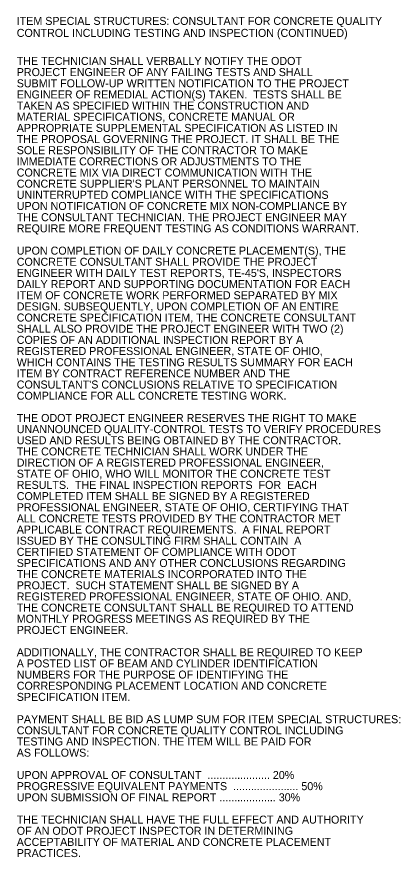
# Model space of a CAD drawing. Extents: x 0 to 55.2, y -1 to 22.
# Drawn here: x 48.5 to 55.22, y -0.99 to 13.7 of the extents above; entities that cross this region are included whole.
import ezdxf

# ---------------------------------------------------------------- set-up
doc = ezdxf.new("R2010")
doc.units = 0
doc.layers.add('SH_Text', color=7, linetype='Continuous')

msp = doc.modelspace()

# ---------------------------------------------------------------- texts
at = {"layer": 'SH_Text'}
for s, p in [('ITEM SPECIAL STRUCTURES: CONSULTANT FOR CONCRETE QUALITY', (48.503, 13.56)), ('CONTROL INCLUDING TESTING AND INSPECTION (CONTINUED)', (48.503, 13.35)), ('THE TECHNICIAN SHALL VERBALLY NOTIFY THE ODOT', (48.503, 12.86)), ('PROJECT ENGINEER OF ANY FAILING TESTS AND SHALL', (48.503, 12.665)), ('SUBMIT FOLLOW-UP WRITTEN NOTIFICATION TO THE PROJECT', (48.503, 12.469)), ('ENGINEER OF REMEDIAL ACTION(S) TAKEN.  TESTS SHALL BE', (48.503, 12.274)), ('TAKEN AS SPECIFIED WITHIN THE CONSTRUCTION AND', (48.503, 12.079)), ('MATERIAL SPECIFICATIONS, CONCRETE MANUAL OR', (48.503, 11.884)), ('APPROPRIATE SUPPLEMENTAL SPECIFICATION AS LISTED IN', (48.503, 11.689)), ('THE PROPOSAL GOVERNING THE PROJECT. IT SHALL BE THE', (48.503, 11.494)), ('SOLE RESPONSIBILITY OF THE CONTRACTOR TO MAKE', (48.503, 11.299)), ('IMMEDIATE CORRECTIONS OR ADJUSTMENTS TO THE', (48.503, 11.104)), ('CONCRETE MIX VIA DIRECT COMMUNICATION WITH THE', (48.503, 10.909)), ("CONCRETE SUPPLIER'S PLANT PERSONNEL TO MAINTAIN", (48.503, 10.714)), ('UNINTERRUPTED COMPLIANCE WITH THE SPECIFICATIONS', (48.503, 10.519)), ('UPON NOTIFICATION OF CONCRETE MIX NON-COMPLIANCE BY', (48.503, 10.324)), ('THE CONSULTANT TECHNICIAN. THE PROJECT ENGINEER MAY', (48.503, 10.128)), ('REQUIRE MORE FREQUENT TESTING AS CONDITIONS WARRANT.', (48.503, 9.933)), ('UPON COMPLETION OF DAILY CONCRETE PLACEMENT(S), THE', (48.503, 9.543)), ('CONCRETE CONSULTANT SHALL PROVIDE THE PROJECT', (48.503, 9.348)), ("ENGINEER WITH DAILY TEST REPORTS, TE-45'S, INSPECTORS", (48.503, 9.153)), ('DAILY REPORT AND SUPPORTING DOCUMENTATION FOR EACH', (48.503, 8.958)), ('ITEM OF CONCRETE WORK PERFORMED SEPARATED BY MIX', (48.503, 8.763)), ('DESIGN. SUBSEQUENTLY, UPON COMPLETION OF AN ENTIRE', (48.503, 8.568)), ('CONCRETE SPECIFICATION ITEM, THE CONCRETE CONSULTANT', (48.503, 8.373)), ('SHALL ALSO PROVIDE THE PROJECT ENGINEER WITH TWO (2)', (48.503, 8.178)), ('COPIES OF AN ADDITIONAL INSPECTION REPORT BY A', (48.503, 7.983)), ('REGISTERED PROFESSIONAL ENGINEER, STATE OF OHIO,', (48.503, 7.788)), ('WHICH CONTAINS THE TESTING RESULTS SUMMARY FOR EACH', (48.503, 7.592)), ('ITEM BY CONTRACT REFERENCE NUMBER AND THE', (48.503, 7.397)), ("CONSULTANT'S CONCLUSIONS RELATIVE TO SPECIFICATION", (48.503, 7.202)), ('COMPLIANCE FOR ALL CONCRETE TESTING WORK.', (48.503, 7.007)), ('THE ODOT PROJECT ENGINEER RESERVES THE RIGHT TO MAKE', (48.503, 6.617)), ('UNANNOUNCED QUALITY-CONTROL TESTS TO VERIFY PROCEDURES', (48.503, 6.422)), ('USED AND RESULTS BEING OBTAINED BY THE CONTRACTOR. ', (48.503, 6.227)), ('THE CONCRETE TECHNICIAN SHALL WORK UNDER THE', (48.503, 6.032)), ('DIRECTION OF A REGISTERED PROFESSIONAL ENGINEER,', (48.503, 5.837)), ('STATE OF OHIO, WHO WILL MONITOR THE CONCRETE TEST', (48.503, 5.642)), ('RESULTS.  THE FINAL INSPECTION REPORTS  FOR  EACH', (48.503, 5.447)), ('COMPLETED ITEM SHALL BE SIGNED BY A REGISTERED', (48.503, 5.251)), ('PROFESSIONAL ENGINEER, STATE OF OHIO, CERTIFYING THAT', (48.503, 5.056)), ('ALL CONCRETE TESTS PROVIDED BY THE CONTRACTOR MET', (48.503, 4.861)), ('APPLICABLE CONTRACT REQUIREMENTS.  A FINAL REPORT', (48.503, 4.666)), ('ISSUED BY THE CONSULTING FIRM SHALL CONTAIN  A', (48.503, 4.471)), ('CERTIFIED STATEMENT OF COMPLIANCE WITH ODOT', (48.503, 4.276)), ('SPECIFICATIONS AND ANY OTHER CONCLUSIONS REGARDING', (48.503, 4.081)), ('THE CONCRETE MATERIALS INCORPORATED INTO THE', (48.503, 3.886)), ('PROJECT.  SUCH STATEMENT SHALL BE SIGNED BY A', (48.503, 3.691)), ('REGISTERED PROFESSIONAL ENGINEER, STATE OF OHIO. AND,', (48.503, 3.496)), ('THE CONCRETE CONSULTANT SHALL BE REQUIRED TO ATTEND', (48.503, 3.301)), ('MONTHLY PROGRESS MEETINGS AS REQUIRED BY THE', (48.503, 3.106)), ('PROJECT ENGINEER.', (48.503, 2.911)), ('ADDITIONALLY, THE CONTRACTOR SHALL BE REQUIRED TO KEEP', (48.503, 2.52)), ('A POSTED LIST OF BEAM AND CYLINDER IDENTIFICATION', (48.503, 2.325)), ('NUMBERS FOR THE PURPOSE OF IDENTIFYING THE', (48.503, 2.13)), ('CORRESPONDING PLACEMENT LOCATION AND CONCRETE', (48.503, 1.935)), ('SPECIFICATION ITEM.', (48.503, 1.74)), ('PAYMENT SHALL BE BID AS LUMP SUM FOR ITEM SPECIAL STRUCTURES:', (48.503, 1.35)), ('CONSULTANT FOR CONCRETE QUALITY CONTROL INCLUDING', (48.503, 1.155)), ('TESTING AND INSPECTION. THE ITEM WILL BE PAID FOR', (48.503, 0.96)), ('AS FOLLOWS:', (48.503, 0.765)), ('UPON APPROVAL OF CONSULTANT  ..................... 20%', (48.503, 0.374)), ('PROGRESSIVE EQUIVALENT PAYMENTS  ...................... 50%', (48.503, 0.179)), ('UPON SUBMISSION OF FINAL REPORT ................... 30%', (48.503, -0.016)), ('THE TECHNICIAN SHALL HAVE THE FULL EFFECT AND AUTHORITY', (48.503, -0.406)), ('OF AN ODOT PROJECT INSPECTOR IN DETERMINING', (48.503, -0.601)), ('ACCEPTABILITY OF MATERIAL AND CONCRETE PLACEMENT', (48.503, -0.796)), ('PRACTICES.', (48.503, -0.991))]:
    msp.add_text(s, height=0.14, dxfattribs=at).set_placement(p)

doc.saveas('drawing.dxf')
